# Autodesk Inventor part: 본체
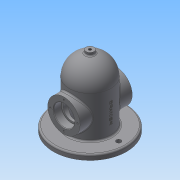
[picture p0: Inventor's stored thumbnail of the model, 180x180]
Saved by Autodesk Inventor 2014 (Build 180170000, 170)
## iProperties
Created: 2019-11
Part Number: 본체
Material: 일반
Document SubType Name: Modeling
Designer: net
Density: 1 g/cm^3
Appearance: 기본값
Author: net
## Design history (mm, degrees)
sketch "스케치1"
  geometry: C1 r 70 at (0, 0); 1 further point
  constraints: 1 centre point, 1 coincident
  dimensions: "d0" = 140 diameter of C1
extrude "돌출1" new body sketch "스케치1" distance "d1" = 10; taper "d2" = 0 deg
sketch "스케치2"
  geometry: C1 r 70 at (0, 0) reference; C2 r 40 at (0, 0)
  constraints: 1 centre point, 1 coincident
  dimensions: "d3" = 80 diameter of C2
extrude "돌출2" join sketch "스케치2" distance "d4" = 80; taper "d5" = 0 deg
sketch "스케치3"
  geometry: L1 (-70, 0)-(-70, 10) reference; L2 (-70, 10)-(-40, 10) reference; L3 (-40, 10)-(-40, 90) reference; L4 (-40, 90)-(40, 90) reference; L5 (40, 90)-(40, 10) reference; L6 (40, 10)-(70, 10) reference; L7 (70, 10)-(70, 0) reference; L8 (70, 0)-(-70, 0) reference; L9 (0, 90)-(0, 130); L10 (0, 90)-(0, 130); L11 (0, 90)-(40, 90); A1 r 40 centre (0, 90) between (40, 90) and (0, 130); 1 further point
  constraints: 6 end point, 2 perpendicular, 2 point on circle, 1 centre point, 1 coincident, 1 collinear, 1 midpoint
  dimensions: "d6" = 40 distance of L9.start L9.end
revolve "회전1" sketch "스케치3" stored, may be unused: angle "d7" = 90 deg
feature "쉘1" dims "d16" = 10
node "작업 평면1"
sketch "스케치4"
  geometry: L1 (40, 90)-(-40, 90) reference; L2 (-40, 10)-(40, 10) reference; L3 (-70, 0)-(70, 0) reference; C1 r 31 at (0, 50); 2 further points
  constraints: 1 centre point, 1 midpoint, 1 vertical alignment
  dimensions: "d9" = 62 diameter of C1; "d10" = 50 distance from line of L3 C1.centre
extrude "돌출3" join sketch "스케치4" stored distance "d11" = 90; taper "d12" = 0 deg
sketch "스케치5"
  geometry: C1 r 31 at (0, 0) reference; C2 r 20 at (0, 0); 1 further point
  constraints: 1 centre point, 1 coincident
  dimensions: "d13" = 40 diameter of C2
extrude "돌출4" cut sketch "스케치5" distance "d14" = 15; taper "d15" = 0 deg
sketch "스케치6"
  geometry: C1 r 20 at (0, 0) reference; C2 r 16.5 at (0, 0); 1 further point
  constraints: 1 centre point, 1 coincident
  dimensions: "d17" = 33 diameter of C2
extrude "돌출5" cut sketch "스케치6" distance "d18" = 34.75; taper "d19" = 0 deg
sketch "스케치7"
  geometry: C1 r 31 at (0, 0) reference; C2 r 20 at (0, 0); 1 further point
  constraints: 1 centre point, 1 coincident
  dimensions: "d20" = 40 diameter of C2
extrude "돌출6" cut sketch "스케치7" distance "d21" = 15; taper "d22" = 0 deg
sketch "스케치8"
  geometry: C1 r 20 at (0, 0) reference; C2 r 16.5 at (0, 0); 1 further point
  constraints: 1 centre point, 1 coincident
  dimensions: "d23" = 33 diameter of C2
extrude "돌출7" cut sketch "스케치8" distance "d24" = 15; taper "d25" = 0 deg
sketch "스케치9" dims "d26" = 52
  geometry: C1 r 20 at (0, 0) reference; 3 further points
  constraints: 2 vertical alignment, 1 coincident, 2 other
hole "구멍1" sketch "스케치9" at (0, -26) diameter "d27" = 3.242; stored, may be unused: countersink angle "d31" = 82 deg, drill point angle "d33" = 118 deg; dims "d28" = 8, "d29" = 3.023, "d30" = 2, "d32" = 10
sketch "스케치10" dims "d37" = 52
  geometry: C1 r 31 at (0, 0) reference; 3 further points
  constraints: 2 vertical alignment, 1 coincident, 2 other
hole "구멍2" sketch "스케치10" at (0, 26) diameter "d38" = 3.242; stored, may be unused: countersink angle "d42" = 82 deg, drill point angle "d44" = 118 deg; dims "d39" = 8, "d40" = 3.023, "d41" = 2, "d43" = 10
node "작업 평면3"
sketch "스케치11"
  geometry: C1 r 40 at (0, 0) reference; C2 r 7.5 at (0, 0); 1 further point
  constraints: 1 centre point, 1 coincident
  dimensions: "d49" = 15 diameter of C2
extrude "돌출8" join sketch "스케치11" stored distance "d50" = 15; taper "d51" = 0 deg
sketch "스케치12"
  geometry: C1 r 7.5 at (0, 0) reference; 1 further point
  constraints: 1 coincident
hole "구멍3" sketch "스케치12" at (0, 0) diameter "d52" = 5.188; stored, may be unused: countersink angle "d56" = 82 deg, drill point angle "d58" = 118 deg; dims "d53" = 33, "d54" = 3.023, "d55" = 2, "d57" = 33.75
sketch "스케치13"
  geometry: C1 r 40 at (0, 0) reference; C2 r 4.5 at (55, 0); C3 r 4.5 at (-55, 0)
  constraints: 2 centre point, 2 horizontal alignment
  dimensions: "d59" = 9 diameter of C2; "d60" = 9 diameter of C3; "d61" = 55 distance of C1.centre C3.centre; "d62" = 55 distance of C1.centre C2.centre
extrude "돌출9" cut sketch "스케치13" distance "d63" = 15; taper "d64" = 0 deg
node "작업 평면4"
sketch "스케치14"
  geometry: L1 (-70, 0)-(70, 0) reference; 3 further points
  constraints: 1 midpoint, 1 vertical alignment, 1 other
  dimensions: "d67" = 50 distance of point (0, 0) point (0, 50)
feature "엠보싱1" sketch "스케치14" dims "d2" = 0, "d68" = 0.5, "d69" = 0
fillet "모깎기1" dims "d70" = 0.3
fillet "모깎기2" dims "d71" = 3
chamfer "모따기1" distance "d72" = 1; stored, may be unused: second distance "d73" = 2, angle "d74" = 45 deg
chamfer "모따기2" distance "d75" = 1; stored, may be unused: second distance "d76" = 2, angle "d77" = 45 deg
node "솔리드1"
mirror "대칭1"
pattern_circular "원형 패턴1" dims angle "d35" = 360 deg
pattern_circular "원형 패턴2" dims angle "d46" = 360 deg
node "투영된 루프1"
node "작업 평면2"
node "투영된 루프2"
node "절단 모서리 투영1"
other parameters: "d48" = -135
